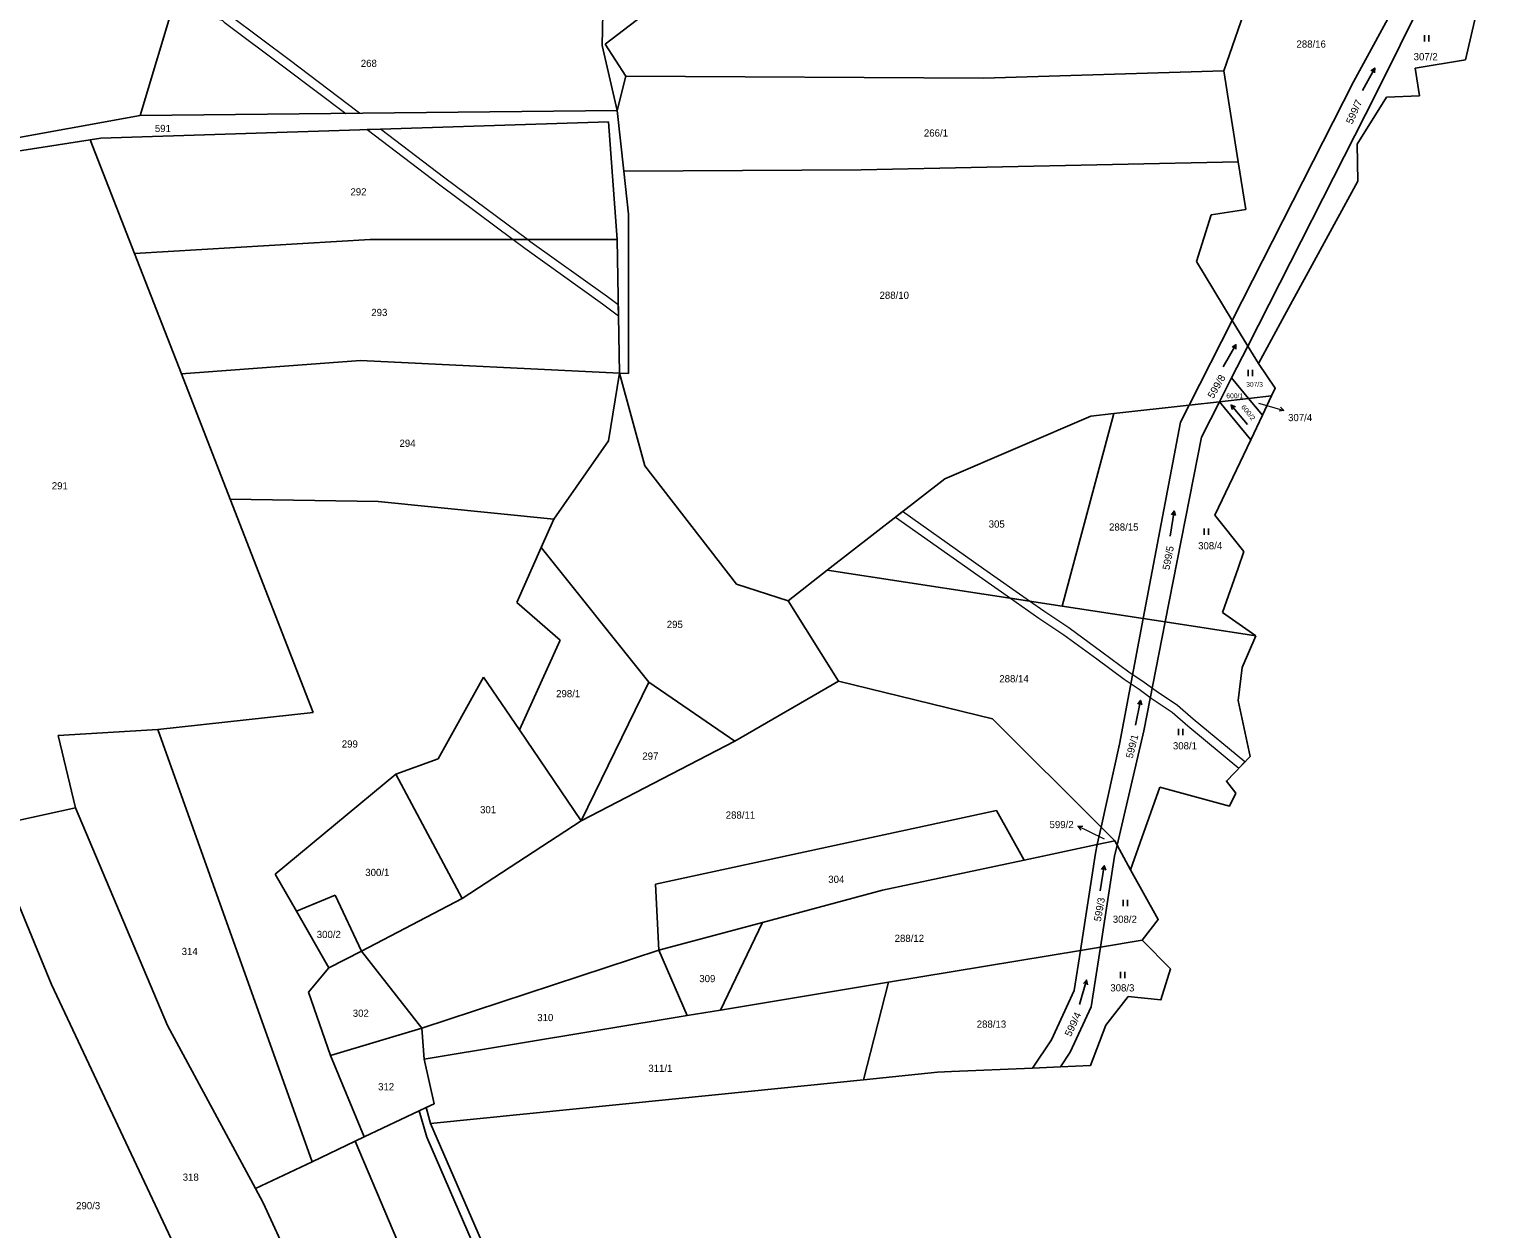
# Model space of a CAD drawing. Extents: x -664548 to -662415, y -1069720 to -1068208.
# Drawn here: x -662952.7 to -662608.4, y -1069185.2 to -1068901.8 of the extents above; entities that cross this region are included whole.
import ezdxf
from ezdxf.enums import TextEntityAlignment as Align

# ---------------------------------------------------------------- set-up
doc = ezdxf.new("R2010")
doc.units = 0
doc.header["$LTSCALE"] = 0.68
for name, color, linetype, lineweight in [('1', 7, 'Continuous', 25), ('13', 7, 'Continuous', 13), ('3', 7, 'Continuous', 25), ('7', 7, 'Continuous', 13)]:
    doc.layers.add(name, color=color, linetype=linetype, lineweight=lineweight)
doc.layers.add('2', color=7, linetype='Continuous')

msp = doc.modelspace()

# ---------------------------------------------------------------- linework, layer by layer
at = {"layer": '1'}
for p, q in [((-662639.86, -1068914.29), (-662611.56, -1068862.04)), ((-662634.51, -1068917.01), (-662608.55, -1068864.58)), ((-662670.53, -1068911.69), (-662661.44, -1068885.59)), ((-662816.62, -1068905.4), (-662792.31, -1068886.74)), ((-662608.4, -1068887.26), (-662613.44, -1068909.09)), ((-662926.47, -1068922.26), (-662917.67, -1068892.82)), ((-662816.96, -1068889.63), (-662817.37, -1068905.73)), ((-662817.37, -1068905.73), (-662813.84, -1068921.1)), ((-662811.75, -1068912.95), (-662816.62, -1068905.4)), ((-662613.44, -1068909.09), (-662625.31, -1068911.09)), ((-662813.84, -1068921.1), (-662811.75, -1068912.95)), ((-662811.75, -1068912.95), (-662727.3, -1068913.46)), ((-662727.3, -1068913.46), (-662670.53, -1068911.69)), ((-662670.53, -1068911.69), (-662667.12, -1068933.19)), ((-662625.31, -1068911.09), (-662624.29, -1068917.61)), ((-662668.54, -1068970.68), (-662639.86, -1068914.29)), ((-662664.88, -1068976.71), (-662634.51, -1068917.01)), ((-662632.09, -1068917.91), (-662639.04, -1068928.98)), ((-662624.29, -1068917.61), (-662632.09, -1068917.91)), ((-662992.7, -1068934.25), (-662926.47, -1068922.26)), ((-662935.78, -1068927.63), (-662815.89, -1068923.74)), ((-662926.47, -1068922.26), (-662813.84, -1068921.1)), ((-662815.89, -1068923.74), (-662813.84, -1068951.57)), ((-662813.84, -1068921.1), (-662812.26, -1068935.37)), ((-662959.42, -1068931.3), (-662938.25, -1068928.01)), ((-662938.25, -1068928.01), (-662935.78, -1068927.63)), ((-662927.79, -1068954.86), (-662938.25, -1068928.01)), ((-662639.04, -1068928.98), (-662638.84, -1068937.79)), ((-662756.15, -1068935.05), (-662667.12, -1068933.19)), ((-662667.12, -1068933.19), (-662665.33, -1068944.48)), ((-662756.15, -1068935.05), (-662812.26, -1068935.37)), ((-662812.26, -1068935.37), (-662811.13, -1068945.53)), ((-662638.84, -1068937.79), (-662656.19, -1068969.52)), ((-662665.33, -1068944.48), (-662673.49, -1068945.69)), ((-662811.13, -1068983.22), (-662811.13, -1068945.53)), ((-662673.49, -1068945.69), (-662677.01, -1068956.77)), ((-662872.12, -1068951.57), (-662927.79, -1068954.86)), ((-662813.84, -1068951.57), (-662872.12, -1068951.57)), ((-662813.23, -1068983.12), (-662813.84, -1068951.57)), ((-662916.72, -1068983.27), (-662927.79, -1068954.86)), ((-662668.54, -1068970.68), (-662677.01, -1068956.77)), ((-662678.71, -1068990.67), (-662668.54, -1068970.68)), ((-662664.88, -1068976.71), (-662668.54, -1068970.68)), ((-662656.19, -1068969.52), (-662662.37, -1068980.83)), ((-662668.7, -1068984.22), (-662664.88, -1068976.71)), ((-662662.37, -1068980.83), (-662664.88, -1068976.71)), ((-662874.43, -1068980.12), (-662916.72, -1068983.27)), ((-662813.23, -1068983.12), (-662874.43, -1068980.12)), ((-662905.2, -1069012.85), (-662916.72, -1068983.27)), ((-662815.89, -1068999.08), (-662813.23, -1068983.12)), ((-662811.13, -1068983.22), (-662813.23, -1068983.12)), ((-662807.28, -1069004.96), (-662813.23, -1068983.12)), ((-662671.57, -1068989.87), (-662668.7, -1068984.22)), ((-662668.7, -1068984.22), (-662664.68, -1068989.1)), ((-662671.57, -1068989.87), (-662664.68, -1068989.1)), ((-662664.68, -1068989.1), (-662659.25, -1068988.49)), ((-662664.68, -1068989.1), (-662661.42, -1068993.06)), ((-662659.25, -1068988.49), (-662661.42, -1068993.06)), ((-662708.69, -1069038.16), (-662696.53, -1068992.67)), ((-662701.93, -1068993.27), (-662696.53, -1068992.67)), ((-662696.53, -1068992.67), (-662678.71, -1068990.67)), ((-662680.74, -1068994.66), (-662678.71, -1068990.67)), ((-662678.71, -1068990.67), (-662671.57, -1068989.87)), ((-662675.8, -1068998.19), (-662671.57, -1068989.87)), ((-662671.57, -1068989.87), (-662664.18, -1068998.85)), ((-662736.39, -1069008.03), (-662701.93, -1068993.27)), ((-662689.56, -1069041.08), (-662680.74, -1068994.66)), ((-662661.42, -1068993.06), (-662664.18, -1068998.85)), ((-662828.79, -1069017.62), (-662815.89, -1068999.08)), ((-662684.37, -1069041.87), (-662675.8, -1068998.19)), ((-662785.65, -1069032.92), (-662807.28, -1069004.96)), ((-662764.19, -1069029.67), (-662736.39, -1069008.03)), ((-662870.22, -1069013.41), (-662905.2, -1069012.85)), ((-662885.58, -1069063.24), (-662905.2, -1069012.85)), ((-662828.79, -1069017.62), (-662870.22, -1069013.41)), ((-662831.75, -1069024.28), (-662828.79, -1069017.62)), ((-662837.51, -1069037.27), (-662831.75, -1069024.28)), ((-662806.33, -1069056.09), (-662831.75, -1069024.28)), ((-662665.76, -1069025.22), (-662667.15, -1069029.2)), ((-662773.43, -1069036.86), (-662764.19, -1069029.67)), ((-662708.69, -1069038.16), (-662764.19, -1069029.67)), ((-662667.15, -1069029.2), (-662670.8, -1069039.64)), ((-662773.43, -1069036.86), (-662785.65, -1069032.92)), ((-662827.25, -1069046.18), (-662837.51, -1069037.27)), ((-662761.53, -1069055.85), (-662773.43, -1069036.86)), ((-662689.56, -1069041.08), (-662708.69, -1069038.16)), ((-662695.19, -1069070.72), (-662689.56, -1069041.08)), ((-662684.37, -1069041.87), (-662689.56, -1069041.08)), ((-662670.8, -1069039.64), (-662662.96, -1069045.15)), ((-662689.42, -1069067.61), (-662684.37, -1069041.87)), ((-662662.96, -1069045.15), (-662684.37, -1069041.87)), ((-662827.25, -1069046.18), (-662836.91, -1069067.35)), ((-662662.96, -1069045.15), (-662666.17, -1069052.64)), ((-662856.1, -1069074.21), (-662845.34, -1069054.91)), ((-662836.91, -1069067.35), (-662845.34, -1069054.91)), ((-662806.33, -1069056.09), (-662822.33, -1069088.86)), ((-662786.03, -1069070.07), (-662806.33, -1069056.09)), ((-662786.03, -1069070.07), (-662761.53, -1069055.85)), ((-662761.53, -1069055.85), (-662725.14, -1069064.79)), ((-662922.26, -1069067.31), (-662885.58, -1069063.24)), ((-662725.14, -1069064.79), (-662699.51, -1069090.34)), ((-662945.8, -1069068.68), (-662922.26, -1069067.31)), ((-662885.88, -1069169.38), (-662922.26, -1069067.31)), ((-662822.33, -1069088.86), (-662836.91, -1069067.35)), ((-662695.74, -1069094.56), (-662689.42, -1069067.61)), ((-662941.76, -1069085.76), (-662945.8, -1069068.68)), ((-662822.33, -1069088.86), (-662786.03, -1069070.07)), ((-662699.51, -1069090.34), (-662695.19, -1069070.72)), ((-662866.09, -1069077.84), (-662856.1, -1069074.21)), ((-662894.59, -1069101.41), (-662866.09, -1069077.84)), ((-662850.38, -1069107.2), (-662866.09, -1069077.84)), ((-662685.67, -1069080.89), (-662690.3, -1069093.95)), ((-662956.09, -1069088.9), (-662941.76, -1069085.76)), ((-662941.76, -1069085.76), (-662920, -1069137.17)), ((-662850.38, -1069107.2), (-662822.33, -1069088.86)), ((-662804.78, -1069103.81), (-662724.23, -1069086.43)), ((-662724.23, -1069086.43), (-662717.65, -1069098.11)), ((-662947.44, -1069127.48), (-662962.74, -1069090.35)), ((-662700.41, -1069094.44), (-662699.51, -1069090.34)), ((-662699.51, -1069090.34), (-662696.28, -1069093.56)), ((-662717.65, -1069098.11), (-662700.41, -1069094.44)), ((-662700.87, -1069096.52), (-662700.41, -1069094.44)), ((-662700.41, -1069094.44), (-662696.28, -1069093.56)), ((-662696.36, -1069097.21), (-662695.74, -1069094.56)), ((-662696.28, -1069093.56), (-662695.74, -1069094.56)), ((-662695.74, -1069094.56), (-662692.59, -1069100.41)), ((-662690.3, -1069093.95), (-662692.59, -1069100.41)), ((-662751.14, -1069105.23), (-662717.65, -1069098.11)), ((-662704.39, -1069119.49), (-662700.87, -1069096.52)), ((-662699.66, -1069118.7), (-662696.36, -1069097.21)), ((-662894.59, -1069101.41), (-662889.58, -1069110.15)), ((-662880.41, -1069106.4), (-662889.58, -1069110.15)), ((-662880.41, -1069106.4), (-662874.2, -1069119.61)), ((-662803.93, -1069119.4), (-662804.78, -1069103.81)), ((-662751.14, -1069105.23), (-662779.45, -1069112.83)), ((-662874.2, -1069119.61), (-662850.38, -1069107.2)), ((-662889.58, -1069110.15), (-662881.87, -1069123.6)), ((-662779.45, -1069112.83), (-662803.93, -1069119.4)), ((-662789.39, -1069133.56), (-662779.45, -1069112.83)), ((-662881.87, -1069123.6), (-662874.2, -1069119.61)), ((-662874.2, -1069119.61), (-662859.91, -1069137.85)), ((-662859.91, -1069137.85), (-662803.93, -1069119.4)), ((-662803.93, -1069119.4), (-662797.25, -1069134.86)), ((-662749.71, -1069126.99), (-662704.39, -1069119.49)), ((-662705.84, -1069128.9), (-662704.39, -1069119.49)), ((-662704.39, -1069119.49), (-662699.66, -1069118.7)), ((-662701.82, -1069132.78), (-662699.66, -1069118.7)), ((-662699.66, -1069118.7), (-662689.81, -1069117.07)), ((-662881.87, -1069123.6), (-662886.71, -1069129.31)), ((-662789.39, -1069133.56), (-662749.71, -1069126.99)), ((-662749.71, -1069126.99), (-662755.62, -1069149.99)), ((-662888.64, -1069252.46), (-662947.44, -1069127.48)), ((-662886.71, -1069129.31), (-662881.51, -1069144.27)), ((-662711.26, -1069140.54), (-662705.84, -1069128.9)), ((-662797.25, -1069134.86), (-662789.39, -1069133.56)), ((-662706.81, -1069143.49), (-662701.82, -1069132.78)), ((-662920, -1069137.17), (-662899.2, -1069175.71)), ((-662859.43, -1069145.16), (-662797.25, -1069134.86)), ((-662859.91, -1069137.85), (-662881.51, -1069144.27)), ((-662859.43, -1069145.16), (-662859.91, -1069137.85)), ((-662711.26, -1069140.54), (-662715.71, -1069147.26)), ((-662881.51, -1069144.27), (-662873.54, -1069163.51)), ((-662706.81, -1069143.49), (-662709.11, -1069146.98)), ((-662857.03, -1069155.66), (-662859.43, -1069145.16)), ((-662715.71, -1069147.26), (-662734.84, -1069148.08)), ((-662709.11, -1069146.98), (-662715.71, -1069147.26)), ((-662702, -1069146.67), (-662709.11, -1069146.98)), ((-662755.62, -1069149.99), (-662789.89, -1069153.47)), ((-662738.14, -1069148.22), (-662755.62, -1069149.99)), ((-662734.84, -1069148.08), (-662738.14, -1069148.22)), ((-662873.54, -1069163.51), (-662860.56, -1069157.34)), ((-662860.56, -1069157.34), (-662858.95, -1069156.57)), ((-662858.78, -1069163.55), (-662860.56, -1069157.34)), ((-662858.95, -1069156.57), (-662857.03, -1069155.66)), ((-662857.86, -1069160.37), (-662858.95, -1069156.57)), ((-662885.88, -1069169.38), (-662875.68, -1069164.53)), ((-662875.68, -1069164.53), (-662873.54, -1069163.51)), ((-662854.01, -1069215.69), (-662875.68, -1069164.53)), ((-662847.01, -1069190.67), (-662858.78, -1069163.55)), ((-662899.2, -1069175.71), (-662885.88, -1069169.38)), ((-662899.2, -1069175.71), (-662897.41, -1069179.04)), ((-662897.41, -1069179.04), (-662859.82, -1069260.43))]:
    msp.add_line(p, q, dxfattribs=at)
for points in [[(-662662.37, -1068980.83), (-662658.38, -1068986.66), (-662659.25, -1068988.49)], [(-662664.18, -1068998.85), (-662672.64, -1069016.63), (-662665.76, -1069025.22)], [(-662666.17, -1069052.64), (-662667.12, -1069060.44), (-662664.34, -1069073.69)], [(-662664.34, -1069073.69), (-662669.91, -1069079.45), (-662667.66, -1069082.3)], [(-662667.66, -1069082.3), (-662669.2, -1069085.38), (-662685.67, -1069080.89)], [(-662692.59, -1069100.41), (-662686.01, -1069112.15), (-662689.81, -1069117.07)], [(-662689.81, -1069117.07), (-662683.12, -1069123.84), (-662685.38, -1069131.15), (-662693.14, -1069130.37)], [(-662693.14, -1069130.37), (-662698.4, -1069137.14), (-662702, -1069146.67)], [(-662789.89, -1069153.47), (-662857.86, -1069160.37), (-662845.08, -1069189.83)]]:
    msp.add_lwpolyline(points, dxfattribs=at)
at = {"layer": '13'}
for points in [[(-662907.96, -1068899.47), (-662907.16, -1068899.69), (-662907.02, -1068899.77), (-662906.63, -1068900.17), (-662892.2, -1068910.96), (-662877.92, -1068921.76), (-662874.66, -1068921.73), (-662875.31, -1068921.23), (-662891, -1068909.36), (-662905.31, -1068898.65), (-662905.78, -1068898.19), (-662906.36, -1068897.83), (-662907.44, -1068897.55), (-662918.17, -1068894.51), (-662918.75, -1068896.42)], [(-662855.7, -1068938.62), (-662838.36, -1068951.57), (-662835.01, -1068951.57), (-662854.5, -1068937.02), (-662869.71, -1068925.49), (-662872.87, -1068925.59)], [(-662817.27, -1068966.71), (-662813.49, -1068969.53), (-662813.54, -1068966.99), (-662816.09, -1068965.09), (-662834.46, -1068951.98), (-662835.01, -1068951.57), (-662838.36, -1068951.57), (-662835.64, -1068953.6)], [(-662728.33, -1069031.07), (-662720.9, -1069036.29), (-662716.44, -1069036.97), (-662727.17, -1069029.43), (-662746.4, -1069015.82), (-662748.04, -1069017.1)], [(-662694.1, -1069055.38), (-662690.48, -1069057.78), (-662687.65, -1069059.84), (-662682.72, -1069063.21), (-662679.03, -1069066.37), (-662666.96, -1069076.4), (-662665.56, -1069074.95), (-662677.75, -1069064.85), (-662681.5, -1069061.63), (-662686.49, -1069058.2), (-662689.34, -1069056.14), (-662692.94, -1069053.74), (-662699.35, -1069048.99), (-662707.15, -1069043.27), (-662713.06, -1069039.35), (-662716.44, -1069036.97), (-662720.9, -1069036.29), (-662714.18, -1069041.01), (-662708.29, -1069044.91), (-662700.53, -1069050.59)]]:
    msp.add_lwpolyline(points, close=True, dxfattribs=at)
at = {"layer": '3'}
for p, q in [((-662623.111, -1068904.75), (-662623.111, -1068903.25)), ((-662622.11, -1068904.75), (-662622.11, -1068903.25)), ((-662634.87, -1068911.065), (-662634.905, -1068912.163)), ((-662667.664, -1068976.381), (-662667.718, -1068977.478)), ((-662664.751, -1068983.84), (-662664.751, -1068982.34)), ((-662663.75, -1068983.84), (-662663.75, -1068982.34)), ((-662668.803, -1068990.643), (-662667.791, -1068991.069)), ((-662682.27, -1069015.701), (-662681.927, -1069016.745)), ((-662675.181, -1069021.3), (-662675.181, -1069019.8)), ((-662674.18, -1069021.3), (-662674.18, -1069019.8)), ((-662690.174, -1069060.421), (-662689.887, -1069061.481)), ((-662681.211, -1069068.65), (-662681.211, -1069067.15)), ((-662680.21, -1069068.65), (-662680.21, -1069067.15)), ((-662698.77, -1069099.471), (-662698.427, -1069100.515)), ((-662694.261, -1069108.98), (-662694.261, -1069107.48)), ((-662693.26, -1069108.98), (-662693.26, -1069107.48)), ((-662702.94, -1069126.482), (-662702.727, -1069127.56)), ((-662694.931, -1069125.98), (-662694.931, -1069124.48)), ((-662693.93, -1069125.98), (-662693.93, -1069124.48))]:
    msp.add_line(p, q, dxfattribs=at)
for points in [[(-662637.779, -1068916.313), (-662634.87, -1068911.065), (-662635.782, -1068911.677)], [(-662670.664, -1068981.578), (-662667.664, -1068976.381), (-662668.587, -1068976.977)], [(-662664.946, -1068995.239), (-662668.803, -1068990.643), (-662668.559, -1068991.714)], [(-662683.208, -1069021.627), (-662682.27, -1069015.701), (-662682.918, -1069016.588)], [(-662691.422, -1069066.289), (-662690.174, -1069060.421), (-662690.868, -1069061.272)], [(-662699.708, -1069105.397), (-662698.77, -1069099.471), (-662699.418, -1069100.358)], [(-662704.594, -1069132.25), (-662702.94, -1069126.482), (-662703.691, -1069127.283)]]:
    msp.add_lwpolyline(points, dxfattribs=at)
at = {"layer": '7'}
for p, q in [((-662656.345, -1068991.887), (-662657.17, -1068991.13)), ((-662704.977, -1069090.134), (-662704.297, -1069091.024))]:
    msp.add_line(p, q, dxfattribs=at)
for points in [[(-662662.34, -1068990.17), (-662659.23, -1068991.06), (-662656.345, -1068991.887), (-662657.446, -1068992.092)], [(-662698.67, -1069093.18), (-662702.28, -1069091.45), (-662704.977, -1069090.134), (-662703.858, -1069090.123)]]:
    msp.add_lwpolyline(points, dxfattribs=at)

# ---------------------------------------------------------------- texts
at = {"layer": '2'}
for s, height, p in [('288/16', 1.7, (-662653.36, -1068906.215)), ('268', 1.7, (-662874.36, -1068910.775)), ('307/2', 1.7, (-662625.69, -1068909.205)), ('591', 1.7, (-662923, -1068926.155)), ('266/1', 1.7, (-662741.36, -1068927.225)), ('292', 1.7, (-662876.8, -1068941.125)), ('288/10', 1.7, (-662751.84, -1068965.554)), ('293', 1.7, (-662871.88, -1068969.615)), ('307/3', 1.14, (-662665.23, -1068986.325)), ('600/1', 1.14, (-662669.92, -1068989.035)), ('307/4', 1.7, (-662655.35, -1068994.445)), ('294', 1.7, (-662865.22, -1069000.515)), ('291', 1.7, (-662947.34, -1069010.564)), ('305', 1.7, (-662726.06, -1069019.594)), ('288/15', 1.7, (-662697.63, -1069020.295)), ('308/4', 1.7, (-662676.59, -1069024.725)), ('295', 1.7, (-662802.09, -1069043.304)), ('288/14', 1.7, (-662723.55, -1069056.135)), ('298/1', 1.7, (-662828.22, -1069059.655)), ('299', 1.7, (-662878.85, -1069071.545)), ('308/1', 1.7, (-662682.55, -1069071.975)), ('297', 1.7, (-662807.87, -1069074.405)), ('301', 1.7, (-662846.19, -1069087.064)), ('288/11', 1.7, (-662788.17, -1069088.334)), ('300/1', 1.7, (-662873.3, -1069101.885)), ('304', 1.7, (-662763.95, -1069103.515)), ('308/2', 1.7, (-662696.74, -1069112.935)), ('300/2', 1.7, (-662884.76, -1069116.535)), ('288/12', 1.7, (-662748.27, -1069117.455)), ('314', 1.7, (-662916.67, -1069120.554)), ('309', 1.7, (-662794.41, -1069126.955)), ('308/3', 1.7, (-662697.33, -1069129.145)), ('302', 1.7, (-662876.26, -1069135.135)), ('310', 1.7, (-662832.68, -1069136.165)), ('288/13', 1.7, (-662728.88, -1069137.715)), ('311/1', 1.7, (-662806.45, -1069148.155)), ('312', 1.7, (-662870.27, -1069152.495)), ('318', 1.7, (-662916.42, -1069173.865)), ('290/3', 1.7, (-662941.6, -1069180.594))]:
    msp.add_text(s, height=height, dxfattribs=at).set_placement(p)
for s, height, rotation, width, p in [('599/7', 1.7, 66, 1.05, (-662640.211, -1068924.452)), ('599/8', 1.7, 60, 1.05, (-662673.021, -1068989.262)), ('600/2', 1.14, 309, 1.1, (-662666.511, -1068991.139)), ('599/4', 1.7, 65, 1.05, (-662706.664, -1069139.959))]:
    msp.add_text(s, height=height, rotation=rotation, dxfattribs=dict(at, width=width)).set_placement(p)
for s, rotation, p in [('599/5', 79, (-662683.382, -1069029.691)), ('599/1', 76, (-662692.067, -1069074.202)), ('599/3', 80, (-662699.571, -1069112.733))]:
    msp.add_text(s, height=1.7, rotation=rotation, dxfattribs=at).set_placement(p)
msp.add_text('599/2', height=1.7, dxfattribs=at).set_placement((-662705.99, -1069090.574), align=Align.RIGHT)

doc.saveas('drawing.dxf')
